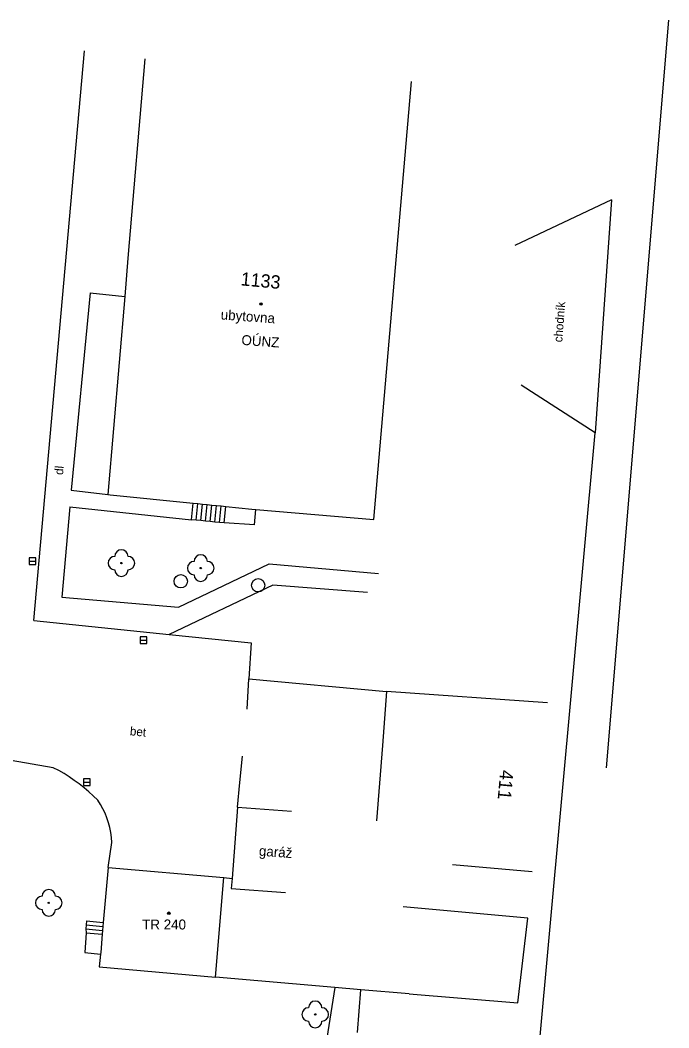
# Model space of a CAD drawing. Extents: x -539244 to -537359, y -1183785 to -1181851.
# Drawn here: x -537407.5 to -537358.9, y -1181941.5 to -1181865.8 of the extents above; entities that cross this region are included whole.
import ezdxf

# ---------------------------------------------------------------- set-up
doc = ezdxf.new("R2010")
doc.units = 0
for name, color, linetype in [('Vrstva 10', 7, 'Continuous'), ('Vrstva 11', 7, 'Continuous'), ('Vrstva 14', 7, 'Continuous'), ('Vrstva 22', 7, 'Continuous'), ('Vrstva 27', 7, 'Continuous'), ('Vrstva 39', 7, 'Continuous'), ('Vrstva 40', 7, 'Continuous'), ('Vrstva 41', 7, 'Continuous'), ('Vrstva 47', 7, 'Continuous'), ('Vrstva 5', 7, 'Continuous'), ('Vrstva 7', 7, 'Continuous')]:
    doc.layers.add(name, color=color, linetype=linetype)

msp = doc.modelspace()

# ---------------------------------------------------------------- linework, layer by layer
at = {"layer": 'Vrstva 10'}
for p, q in [((-537406.48, -1181910.89), (-537402.7, -1181868.13)), ((-537406.48, -1181910.89), (-537396.325, -1181911.931)), ((-537396.325, -1181911.931), (-537390.18, -1181912.57)), ((-537390.18, -1181912.57), (-537390.37, -1181915.27)), ((-537405.03, -1181921.94), (-537408.2, -1181921.41)), ((-537400.92, -1181929.44), (-537400.63, -1181927.55))]:
    msp.add_line(p, q, dxfattribs=at)
for points in [[(-537401.7, -1181924.38), (-537402.028, -1181924.058), (-537402.367, -1181923.748), (-537402.719, -1181923.449), (-537403.081, -1181923.163), (-537403.453, -1181922.89), (-537403.835, -1181922.631), (-537404.226, -1181922.386), (-537404.624, -1181922.155), (-537405.03, -1181921.94)], [(-537400.63, -1181927.55), (-537400.658, -1181927.178), (-537400.709, -1181926.806), (-537400.784, -1181926.436), (-537400.883, -1181926.07), (-537401.004, -1181925.711), (-537401.147, -1181925.36), (-537401.312, -1181925.02), (-537401.497, -1181924.693), (-537401.7, -1181924.38)]]:
    msp.add_lwpolyline(points, dxfattribs=at)
at = {"layer": 'Vrstva 11'}
for p, q in [((-537363.54, -1181921.96), (-537358.851, -1181865.834)), ((-537363.15, -1181879.31), (-537370.41, -1181882.748)), ((-537363.15, -1181879.31), (-537364.37, -1181896.81)), ((-537402.26, -1181886.31), (-537403.69, -1181901.1)), ((-537402.26, -1181886.31), (-537399.67, -1181886.567)), ((-537364.37, -1181896.81), (-537369.923, -1181893.234)), ((-537403.69, -1181901.1), (-537400.93, -1181901.436)), ((-537403.78, -1181902.36), (-537404.39, -1181909.13)), ((-537403.78, -1181902.36), (-537394.65, -1181903.33)), ((-537394.65, -1181903.33), (-537394.525, -1181902.084)), ((-537394.301, -1181903.364), (-537394.176, -1181902.119)), ((-537393.953, -1181903.399), (-537393.828, -1181902.154)), ((-537393.605, -1181903.434), (-537393.48, -1181902.189)), ((-537393.257, -1181903.469), (-537393.132, -1181902.225)), ((-537392.908, -1181903.504), (-537392.783, -1181902.261)), ((-537392.56, -1181903.539), (-537392.435, -1181902.296)), ((-537392.212, -1181903.574), (-537392.087, -1181902.331)), ((-537389.93, -1181903.71), (-537389.832, -1181902.556)), ((-537394.301, -1181903.364), (-537394.65, -1181903.33)), ((-537393.953, -1181903.399), (-537394.301, -1181903.364)), ((-537393.605, -1181903.434), (-537393.953, -1181903.399)), ((-537393.257, -1181903.469), (-537393.605, -1181903.434)), ((-537392.908, -1181903.504), (-537393.257, -1181903.469)), ((-537392.56, -1181903.539), (-537392.908, -1181903.504)), ((-537392.212, -1181903.574), (-537392.56, -1181903.539)), ((-537389.93, -1181903.71), (-537392.212, -1181903.574)), ((-537395.63, -1181909.88), (-537388.83, -1181906.64)), ((-537388.83, -1181906.64), (-537380.62, -1181907.37)), ((-537388.56, -1181908.23), (-537396.325, -1181911.931)), ((-537381.47, -1181908.79), (-537388.56, -1181908.23)), ((-537404.39, -1181909.13), (-537395.63, -1181909.88)), ((-537402.556, -1181933.738), (-537402.582, -1181934.037)), ((-537402.53, -1181933.44), (-537402.556, -1181933.738)), ((-537402.556, -1181933.738), (-537401.307, -1181933.848)), ((-537402.53, -1181933.44), (-537401.282, -1181933.55)), ((-537402.57, -1181934.34), (-537402.67, -1181935.82)), ((-537402.582, -1181934.037), (-537401.332, -1181934.147)), ((-537402.582, -1181934.037), (-537402.57, -1181934.34)), ((-537402.67, -1181935.82), (-537401.484, -1181935.942))]:
    msp.add_line(p, q, dxfattribs=at)
for points in [[(-537373.041, -1181992.065), (-537372.894, -1181990.398), (-537364.37, -1181896.81)], [(-537402.57, -1181934.34), (-537401.357, -1181934.446)]]:
    msp.add_lwpolyline(points, dxfattribs=at)
at = {"layer": 'Vrstva 14'}
for p, q in [((-537383.92, -1181938.44), (-537386.45, -1181954.58)), ((-537382.22, -1181941.81), (-537381.946, -1181938.609))]:
    msp.add_line(p, q, dxfattribs=at)
at = {"layer": 'Vrstva 22'}
for centre in [(-537399.92, -1181906.58), (-537393.97, -1181906.96), (-537405.37, -1181932.08), (-537385.38, -1181940.46)]:
    msp.add_circle(centre, 0.05, dxfattribs=at)
for centre, start, end in [((-537399.92, -1181906.08), 0, 180), ((-537400.42, -1181906.58), 90, 270), ((-537399.42, -1181906.58), 270, 90), ((-537394.47, -1181906.96), 90, 270), ((-537393.97, -1181906.46), 0, 180), ((-537393.47, -1181906.96), 270, 90), ((-537399.92, -1181907.08), 180, 0), ((-537393.97, -1181907.46), 180, 0), ((-537405.37, -1181931.58), 0, 180), ((-537405.87, -1181932.08), 90, 270), ((-537404.87, -1181932.08), 270, 90), ((-537405.37, -1181932.58), 180, 0), ((-537385.38, -1181939.96), 0, 180), ((-537385.88, -1181940.46), 90, 270), ((-537384.88, -1181940.46), 270, 90), ((-537385.38, -1181940.96), 180, 0)]:
    msp.add_arc(centre, 0.5, start, end, dxfattribs=at)
at = {"layer": 'Vrstva 27'}
for p, q in [((-537406.83, -1181906.43), (-537406.33, -1181906.43)), ((-537398.5, -1181912.38), (-537398, -1181912.38)), ((-537402.77, -1181923.02), (-537402.27, -1181923.02))]:
    msp.add_line(p, q, dxfattribs=at)
for points in [[(-537406.83, -1181906.68), (-537406.33, -1181906.68), (-537406.33, -1181906.18), (-537406.83, -1181906.18)], [(-537398.5, -1181912.63), (-537398, -1181912.63), (-537398, -1181912.13), (-537398.5, -1181912.13)], [(-537402.77, -1181923.27), (-537402.27, -1181923.27), (-537402.27, -1181922.77), (-537402.77, -1181922.77)]]:
    msp.add_lwpolyline(points, close=True, dxfattribs=at)
for centre in [(-537395.47, -1181907.95), (-537389.66, -1181908.25)]:
    msp.add_circle(centre, 0.5, dxfattribs=at)
at = {"layer": 'Vrstva 39'}
for centre, radius in [((-537389.448, -1181887.137), 0.09), ((-537389.448, -1181887.137), 0.0398), ((-537396.361, -1181932.859), 0.09), ((-537396.361, -1181932.859), 0.0398)]:
    msp.add_circle(centre, radius, dxfattribs=at)
at = {"layer": 'Vrstva 5'}
for p, q in [((-537380.98, -1181903.31), (-537378.157, -1181870.434)), ((-537400.93, -1181901.436), (-537400.77, -1181901.45)), ((-537390.14, -1181902.53), (-537389.832, -1181902.556)), ((-537389.832, -1181902.556), (-537380.98, -1181903.31)), ((-537380.04, -1181916.21), (-537380.334, -1181920.286)), ((-537367.96, -1181917.08), (-537380.04, -1181916.21)), ((-537380.334, -1181920.286), (-537380.781, -1181925.921)), ((-537391.22, -1181924.89), (-537391.62, -1181930.26)), ((-537391.22, -1181924.89), (-537387.157, -1181925.193)), ((-537375.085, -1181929.197), (-537369.11, -1181929.74)), ((-537400.92, -1181929.44), (-537401.282, -1181933.55)), ((-537400.92, -1181929.44), (-537392.24, -1181930.19)), ((-537392.86, -1181937.65), (-537392.24, -1181930.19)), ((-537391.62, -1181930.26), (-537391.675, -1181931.007)), ((-537391.675, -1181931.007), (-537387.612, -1181931.31)), ((-537401.484, -1181935.942), (-537401.58, -1181936.88)), ((-537401.47, -1181935.81), (-537401.484, -1181935.942)), ((-537401.58, -1181936.88), (-537392.86, -1181937.65))]:
    msp.add_line(p, q, dxfattribs=at)
for points in [[(-537398.16, -1181868.74), (-537399.426, -1181883.688), (-537399.67, -1181886.567), (-537400.93, -1181901.436)], [(-537400.77, -1181901.45), (-537394.525, -1181902.084), (-537394.176, -1181902.119), (-537393.828, -1181902.154), (-537393.48, -1181902.189), (-537393.132, -1181902.225), (-537392.783, -1181902.261), (-537392.435, -1181902.296), (-537392.087, -1181902.331), (-537390.14, -1181902.53)], [(-537401.282, -1181933.55), (-537401.307, -1181933.848), (-537401.332, -1181934.147), (-537401.357, -1181934.446), (-537401.47, -1181935.81)]]:
    msp.add_lwpolyline(points, dxfattribs=at)
at = {"layer": 'Vrstva 7'}
for p, q in [((-537390.49, -1181917.54), (-537390.37, -1181915.27)), ((-537390.37, -1181915.27), (-537380.04, -1181916.21)), ((-537391.03, -1181923.05), (-537390.83, -1181921.08)), ((-537391.22, -1181924.89), (-537391.03, -1181923.05)), ((-537392.24, -1181930.19), (-537391.62, -1181930.26)), ((-537369.427, -1181933.226), (-537378.773, -1181932.377)), ((-537383.92, -1181938.44), (-537392.86, -1181937.65)), ((-537381.946, -1181938.609), (-537383.92, -1181938.44)), ((-537378.32, -1181938.92), (-537381.946, -1181938.609))]:
    msp.add_line(p, q, dxfattribs=at)
msp.add_lwpolyline([(-537378.32, -1181938.92), (-537370.18, -1181939.588), (-537369.427, -1181933.226)], dxfattribs=at)

# ---------------------------------------------------------------- texts
at = {"layer": 'Vrstva 40'}
for s, rotation, p in [('chodník', 85.70999, (-537366.85, -1181890.028)), ('dl', 84.94816, (-537404.302, -1181899.986)), ('bet', 354.47246, (-537399.305, -1181919.498))]:
    msp.add_text(s, height=0.65, rotation=rotation, dxfattribs=at).set_placement(p)
at = {"layer": 'Vrstva 41'}
for s, rotation, p in [('ubytovna', 355.8151, (-537392.488, -1181888.292)), ('OÚNZ', 355.8151, (-537390.935, -1181890.2)), ('garáž', 355.73504, (-537389.623, -1181928.539))]:
    msp.add_text(s, height=0.75, rotation=rotation, dxfattribs=at).set_placement(p)
msp.add_text('TR 240', height=0.75, dxfattribs=at).set_placement((-537398.362, -1181934.083))
at = {"layer": 'Vrstva 47'}
for s, rotation, p in [(' 1133', 354.5908, (-537391.368, -1181885.698)), (' 411', 264.80808, (-537371.46, -1181921.708))]:
    msp.add_text(s, height=1, rotation=rotation, dxfattribs=at).set_placement(p)

doc.saveas('drawing.dxf')
